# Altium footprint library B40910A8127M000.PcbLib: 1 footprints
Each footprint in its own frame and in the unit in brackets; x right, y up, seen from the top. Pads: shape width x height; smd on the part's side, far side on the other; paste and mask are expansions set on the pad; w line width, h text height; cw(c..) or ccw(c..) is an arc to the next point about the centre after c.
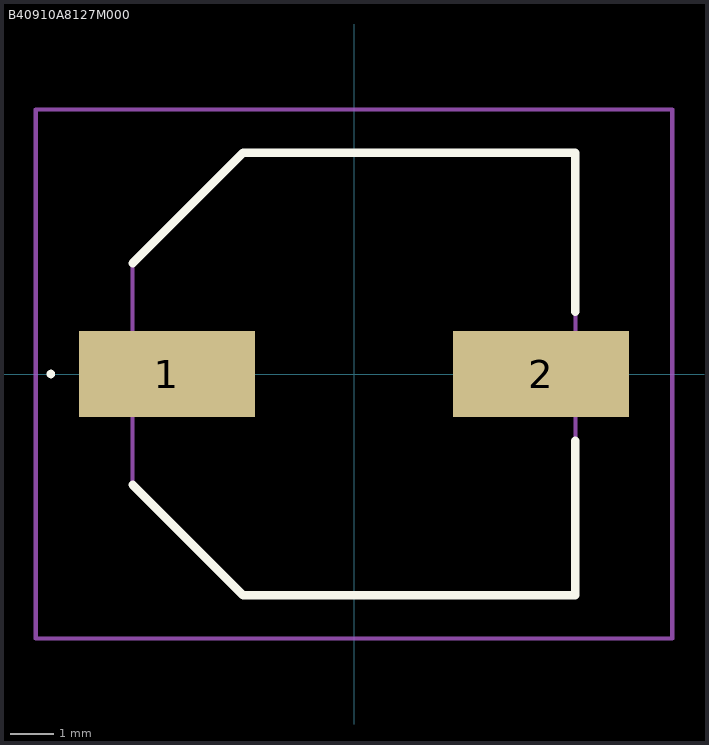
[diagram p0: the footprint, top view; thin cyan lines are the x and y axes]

## B40910A8127M000 [mm]
pads (2):
  rect 4.1x2 smd: 1(-4.35,0) 2(4.35,0)
Top Overlay:
  lines w0.1: -7.1,0 -7.1,0 ; -7.1,0 ccw(c-7.05,0) -7,0 ; -7.1,0 cw(c-7.05,0) -7,0 ; -7,0 -7,0
  lines w0.2: -5.15,-2.575 -2.575,-5.15 5.15,-5.15 ; -5.15,2.575 -2.575,5.15 5.15,5.15 5.15,1.45 ; 4.8,-5.15 5.15,-5.15 ; 5.15,-1.55 5.15,-5.15
Mechanical 15:
  lines w0.1: -5.15,-2.575 -2.575,-5.15 0,-5.15 5.15,-5.15 5.15,5.15 -2.575,5.15 -5.15,2.575 -5.15,-2.575
Mechanical 20:
  lines w0.1: -7.4,-6.15 7.4,-6.15 7.4,6.15 -7.4,6.15 -7.4,-6.15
